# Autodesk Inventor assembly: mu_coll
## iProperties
Shininess: 64.0
Length Units: 11269
Angle Units: 11279
Time Units: 11290
Mass Units: 11283
Length Display Precision: 3
Angle Display Precision: 2
Compacted: True
Created: 2004-08
Part Number: mu_coll
Document SubType Name: Assembly
Designer: John Blackburn
Manufacturer: Standard
Standards Organization: Custom
Density: 0.0
Volumn: 0.0
Area: 0.0
PropertySet Name: Model Information
Control State: 0
Master: False
Checked Out: False
Author: John Blackburn
